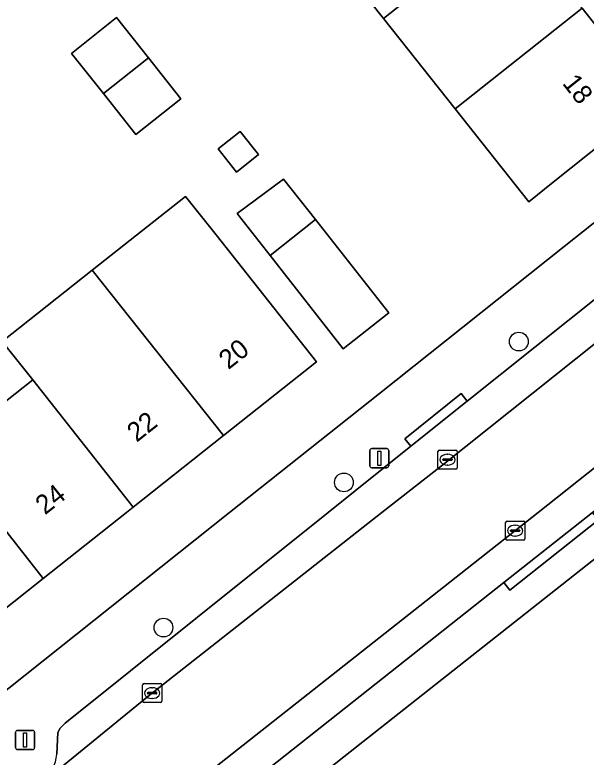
# Model space of a CAD drawing. Extents: x 157320 to 158835, y 386650 to 388491.
# Drawn here: x 157790.58 to 157820.38, y 387487.24 to 387525.96 of the extents above; entities that cross this region are included whole.
import ezdxf

# ---------------------------------------------------------------- set-up
doc = ezdxf.new("R2010")
doc.units = 0
for name, color, linetype in [('IMGEO_Boom', 7, 'Continuous'), ('IMGEO_Erf', 7, 'Continuous'), ('IMGEO_Kolk', 7, 'Continuous'), ('IMGEO_Lichtmast', 7, 'Continuous'), ('IMGEO_Muur', 7, 'Continuous'), ('IMGEO_Pand', 7, 'Continuous'), ('IMGEO_Pand_nummerreeks', 7, 'Continuous'), ('IMGEO_Parkeervlak_open', 7, 'Continuous'), ('IMGEO_Rijbaan_lokaal_open', 7, 'Continuous'), ('IMGEO_Voetpad_open', 7, 'Continuous')]:
    doc.layers.add(name, color=color, linetype=linetype)

msp = doc.modelspace()

# ---------------------------------------------------------------- linework, layer by layer
at = {"layer": 'IMGEO_Boom'}
for centre in [(157816.87, 387508.916), (157807.747, 387501.571), (157798.335, 387493.995)]:
    msp.add_circle(centre, 0.489, dxfattribs=at)
at = {"layer": 'IMGEO_Erf'}
for points in [[(157819.244, 387513.872), (157824.278, 387517.873), (157829.287, 387521.854), (157827.412, 387524.212), (157792.348, 387568.39), (157742.039, 387528.565), (157744.071, 387526.007), (157755.546, 387511.564), (157757.331, 387512.983), (157759.693, 387514.861), (157761.245, 387516.095), (157763.827, 387518.148), (157766.927, 387514.234), (157764.333, 387512.18), (157762.786, 387510.955), (157760.42, 387509.082), (157758.638, 387507.671), (157762.365, 387502.98), (157760.625, 387501.492), (157769.911, 387489.771), (157777.254, 387480.504), (157788.46, 387489.409), (157801.788, 387500), (157809.599, 387506.206)], [(157795.206, 387521.851), (157794.861, 387522.285), (157793.539, 387523.95), (157795.894, 387525.821), (157797.56, 387523.716), (157799.25, 387521.581), (157796.902, 387519.716)], [(157802.34, 387519.882), (157803.298, 387518.673), (157802.146, 387517.759), (157801.188, 387518.968)], [(157804.604, 387517.395), (157806.264, 387515.279), (157810.085, 387510.408), (157807.707, 387508.542), (157803.896, 387513.401), (157802.177, 387515.592)]]:
    msp.add_lwpolyline(points, close=True, dxfattribs=at)
for points in [[(157820.17, 387526.308), (157824.005, 387521.476), (157822.421, 387520.215), (157818.667, 387517.228), (157817.387, 387516.213), (157813.549, 387521.057), (157809.816, 387525.766), (157806.09, 387530.468)], [(157786.817, 387503.193), (157791.52, 387506.918), (157789.921, 387508.912), (157794.619, 387512.633), (157799.489, 387516.491), (157801.076, 387514.487), (157806.326, 387507.853), (157801.472, 387504.011), (157796.76, 387500.28), (157796.406, 387500), (157792.064, 387496.563), (157787.359, 387492.838)], [(157839.124, 387512.036), (157830.533, 387505.25), (157823.234, 387499.485), (157815.987, 387493.76), (157807.747, 387487.251), (157799.439, 387480.688)]]:
    msp.add_lwpolyline(points, dxfattribs=at)
at = {"layer": 'IMGEO_Kolk'}
for p, q in [((157812.726, 387503.256), (157813.578, 387503.256)), ((157812.651, 387502.33), (157812.651, 387503.182)), ((157813.139, 387503.036), (157813.164, 387503.036)), ((157813.652, 387503.182), (157813.652, 387502.33)), ((157812.91, 387502.75), (157812.91, 387502.762)), ((157813.348, 387502.713), (157812.95, 387502.713)), ((157812.953, 387502.799), (157813.351, 387502.799)), ((157813.162, 387502.476), (157813.137, 387502.476)), ((157813.394, 387502.762), (157813.394, 387502.75)), ((157813.578, 387502.256), (157812.726, 387502.256)), ((157816.18, 387498.627), (157816.18, 387499.479)), ((157816.255, 387499.553), (157817.107, 387499.553)), ((157817.181, 387499.479), (157817.181, 387498.627)), ((157816.439, 387499.047), (157816.439, 387499.059)), ((157816.877, 387499.01), (157816.479, 387499.01)), ((157816.482, 387499.096), (157816.88, 387499.096)), ((157816.668, 387499.333), (157816.693, 387499.333)), ((157816.923, 387499.059), (157816.923, 387499.047)), ((157816.691, 387498.773), (157816.666, 387498.773)), ((157817.107, 387498.553), (157816.255, 387498.553)), ((157797.246, 387490.156), (157797.246, 387491.008)), ((157797.321, 387491.082), (157798.173, 387491.082)), ((157797.734, 387490.862), (157797.759, 387490.862)), ((157798.247, 387491.008), (157798.247, 387490.156)), ((157797.505, 387490.576), (157797.505, 387490.588)), ((157797.943, 387490.539), (157797.545, 387490.539)), ((157797.548, 387490.625), (157797.946, 387490.625)), ((157797.989, 387490.588), (157797.989, 387490.576)), ((157798.173, 387490.082), (157797.321, 387490.082)), ((157797.757, 387490.302), (157797.732, 387490.302))]:
    msp.add_line(p, q, dxfattribs=at)
for points in [[(157812.726, 387503.256), (157813.578, 387503.256)], [(157812.651, 387502.33), (157812.651, 387503.182)], [(157813.652, 387503.182), (157813.652, 387502.33)], [(157813.578, 387502.256), (157812.726, 387502.256)], [(157816.18, 387498.627), (157816.18, 387499.479)], [(157816.255, 387499.553), (157817.107, 387499.553)], [(157817.181, 387499.479), (157817.181, 387498.627)], [(157817.107, 387498.553), (157816.255, 387498.553)], [(157797.246, 387490.156), (157797.246, 387491.008)], [(157797.321, 387491.082), (157798.173, 387491.082)], [(157798.247, 387491.008), (157798.247, 387490.156)], [(157798.173, 387490.082), (157797.321, 387490.082)]]:
    msp.add_lwpolyline(points, dxfattribs=at)
for centre, radius, start, end in [((157812.728, 387503.18), 0.0765, 91.552, 178.448), ((157812.728, 387503.18), 0.0765, 91.552, 178.448), ((157813.576, 387503.18), 0.0765, 1.552, 88.448), ((157813.576, 387503.18), 0.0765, 1.552, 88.448), ((157812.95, 387502.759), 0.0403, 85.8775, 175.7526), ((157812.947, 387502.749), 0.0366, 178.938, 274.7102), ((157813.351, 387502.756), 0.043, 264.8664, 352.4533), ((157813.355, 387502.761), 0.0386, 1.7309, 96.639), ((157812.728, 387502.332), 0.0765, 181.552, 268.448), ((157812.728, 387502.332), 0.0765, 181.552, 268.448), ((157813.576, 387502.332), 0.0765, 271.552, 358.448), ((157813.576, 387502.332), 0.0765, 271.552, 358.448), ((157816.257, 387499.477), 0.0765, 91.552, 178.448), ((157816.257, 387499.477), 0.0765, 91.552, 178.448), ((157817.105, 387499.477), 0.0765, 1.552, 88.448), ((157817.105, 387499.477), 0.0765, 1.552, 88.448), ((157816.479, 387499.056), 0.0403, 85.8775, 175.7526), ((157816.476, 387499.046), 0.0366, 178.938, 274.7102), ((157816.88, 387499.053), 0.043, 264.8664, 352.4533), ((157816.884, 387499.058), 0.0386, 1.7309, 96.639), ((157816.257, 387498.629), 0.0765, 181.552, 268.448), ((157816.257, 387498.629), 0.0765, 181.552, 268.448), ((157817.105, 387498.629), 0.0765, 271.552, 358.448), ((157817.105, 387498.629), 0.0765, 271.552, 358.448), ((157797.323, 387491.006), 0.0765, 91.552, 178.448), ((157797.323, 387491.006), 0.0765, 91.552, 178.448), ((157798.171, 387491.006), 0.0765, 1.552, 88.448), ((157798.171, 387491.006), 0.0765, 1.552, 88.448), ((157797.545, 387490.585), 0.0403, 85.8775, 175.7526), ((157797.542, 387490.575), 0.0366, 178.938, 274.7102), ((157797.946, 387490.582), 0.043, 264.8664, 352.4533), ((157797.95, 387490.587), 0.0386, 1.7309, 96.639), ((157797.323, 387490.158), 0.0765, 181.552, 268.448), ((157797.323, 387490.158), 0.0765, 181.552, 268.448), ((157798.171, 387490.158), 0.0765, 271.552, 358.448), ((157798.171, 387490.158), 0.0765, 271.552, 358.448)]:
    msp.add_arc(centre, radius, start, end, dxfattribs=at)
for centre, major_axis, ratio, start_param, end_param in [((157813.138, 387502.756), (-0.387, 0.002), 0.722429, 4.712389, 7.853982), ((157813.163, 387502.756), (-0.39, 0.002), 0.717154, 1.570796, 4.712389), ((157816.667, 387499.053), (-0.387, 0.002), 0.722429, 4.712389, 7.853982), ((157816.692, 387499.053), (-0.39, 0.002), 0.717154, 1.570796, 4.712389), ((157797.733, 387490.582), (-0.387, 0.002), 0.722429, 4.712389, 7.853982), ((157797.758, 387490.582), (-0.39, 0.002), 0.717154, 1.570796, 4.712389)]:
    msp.add_ellipse(centre, major_axis=major_axis, ratio=ratio, start_param=start_param, end_param=end_param, dxfattribs=at)
at = {"layer": 'IMGEO_Lichtmast'}
for p, q in [((157809.097, 387502.432), (157809.097, 387503.232)), ((157809.097, 387503.232), (157809.097, 387502.432)), ((157809.197, 387503.332), (157809.987, 387503.332)), ((157809.987, 387503.332), (157809.197, 387503.332)), ((157810.087, 387503.232), (157810.087, 387502.432)), ((157810.087, 387502.432), (157810.087, 387503.232)), ((157809.987, 387502.332), (157809.197, 387502.332)), ((157809.197, 387502.332), (157809.987, 387502.332)), ((157790.62, 387487.733), (157790.62, 387488.533)), ((157790.62, 387488.533), (157790.62, 387487.733)), ((157790.72, 387488.633), (157791.51, 387488.633)), ((157791.51, 387488.633), (157790.72, 387488.633)), ((157791.61, 387488.533), (157791.61, 387487.733)), ((157791.61, 387487.733), (157791.61, 387488.533)), ((157791.51, 387487.633), (157790.72, 387487.633)), ((157790.72, 387487.633), (157791.51, 387487.633))]:
    msp.add_line(p, q, dxfattribs=at)
for points in [[(157809.517, 387503.207), (157809.667, 387503.207), (157809.667, 387502.457), (157809.517, 387502.457), (157809.517, 387503.207)], [(157791.04, 387488.508), (157791.19, 387488.508), (157791.19, 387487.758), (157791.04, 387487.758), (157791.04, 387488.508)]]:
    msp.add_lwpolyline(points, dxfattribs=at)
for centre, start, end in [((157809.197, 387503.232), 90, 180), ((157809.197, 387503.232), 90, 180), ((157809.987, 387503.232), 0, 90), ((157809.987, 387503.232), 360, 90), ((157809.197, 387502.432), 180, 270), ((157809.197, 387502.432), 180, 270), ((157809.987, 387502.432), 270, 0), ((157809.987, 387502.432), 270, 0), ((157790.72, 387488.533), 90, 180), ((157790.72, 387488.533), 90, 180), ((157791.51, 387488.533), 0, 90), ((157791.51, 387488.533), 360, 90), ((157790.72, 387487.733), 180, 270), ((157790.72, 387487.733), 180, 270), ((157791.51, 387487.733), 270, 0), ((157791.51, 387487.733), 270, 0)]:
    msp.add_arc(centre, 0.1, start, end, dxfattribs=at)
at = {"layer": 'IMGEO_Muur'}
for points in [[(157809.599, 387506.206), (157819.244, 387513.872)], [(157815.987, 387493.76), (157807.747, 387487.251)]]:
    msp.add_lwpolyline(points, dxfattribs=at)
at = {"layer": 'IMGEO_Pand'}
for points in [[(157809.816, 387525.766), (157816.434, 387531.015), (157812.709, 387535.708), (157806.09, 387530.468)], [(157809.816, 387525.766), (157813.549, 387521.057), (157820.17, 387526.308), (157816.434, 387531.015)], [(157820.17, 387526.308), (157813.549, 387521.057), (157817.387, 387516.213), (157818.667, 387517.228), (157822.421, 387520.215), (157824.005, 387521.476)], [(157797.56, 387523.716), (157795.894, 387525.821), (157793.539, 387523.95), (157794.861, 387522.285), (157795.206, 387521.851)], [(157795.206, 387521.851), (157796.902, 387519.716), (157799.25, 387521.581), (157797.56, 387523.716)], [(157801.188, 387518.968), (157802.146, 387517.759), (157803.298, 387518.673), (157802.34, 387519.882)], [(157806.264, 387515.279), (157804.604, 387517.395), (157802.177, 387515.592), (157803.896, 387513.401)], [(157801.472, 387504.011), (157806.326, 387507.853), (157801.076, 387514.487), (157799.489, 387516.491), (157794.619, 387512.633)], [(157806.264, 387515.279), (157803.896, 387513.401), (157807.707, 387508.542), (157810.085, 387510.408)], [(157796.76, 387500.28), (157801.472, 387504.011), (157794.619, 387512.633), (157789.921, 387508.912), (157791.52, 387506.918)], [(157796.76, 387500.28), (157791.52, 387506.918), (157786.817, 387503.193), (157789.344, 387500), (157792.064, 387496.563), (157796.406, 387500)], [(157786.817, 387503.193), (157784.864, 387505.658), (157780.134, 387501.913), (157787.359, 387492.838), (157792.064, 387496.563), (157789.344, 387500)]]:
    msp.add_lwpolyline(points, close=True, dxfattribs=at)
at = {"layer": 'IMGEO_Parkeervlak_open'}
for points in [[(157834.45, 387513.15), (157817.884, 387500), (157797.32, 387483.775)], [(157792.118, 387485.993), (157797.613, 387490.476), (157809.73, 387500), (157812.992, 387502.564), (157824.461, 387511.695)], [(157821.228, 387511.435), (157814.172, 387505.812), (157811.243, 387503.454), (157806.928, 387500), (157793.202, 387489.013), (157792.943, 387488.745), (157792.83, 387488.527), (157792.777, 387487.386)], [(157798.55, 387483.955), (157799.605, 387483.712), (157799.929, 387483.776), (157800.357, 387483.896), (157816.093, 387496.341), (157820.714, 387500), (157833.408, 387510.077)]]:
    msp.add_lwpolyline(points, dxfattribs=at)
msp.add_arc((157790.268, 387487.721), 2.532, 316.9629, 352.4013, dxfattribs=at)
at = {"layer": 'IMGEO_Rijbaan_lokaal_open'}
for points in [[(157839.271, 387523.633), (157837.178, 387521.954), (157830.56, 387516.599), (157826.053, 387512.97), (157824.461, 387511.695), (157812.992, 387502.564), (157809.73, 387500), (157797.613, 387490.476), (157792.118, 387485.993), (157791.581, 387485.489), (157790.953, 387484.901)], [(157796.478, 387483.111), (157797.32, 387483.775), (157817.884, 387500), (157834.45, 387513.15)]]:
    msp.add_lwpolyline(points, dxfattribs=at)
at = {"layer": 'IMGEO_Voetpad_open'}
for points in [[(157826.053, 387512.97), (157830.56, 387516.599), (157829.906, 387517.407), (157836.524, 387522.762), (157835.189, 387524.078), (157830.517, 387520.307), (157829.287, 387521.854), (157824.278, 387517.873), (157819.244, 387513.872), (157809.599, 387506.206), (157801.788, 387500), (157788.46, 387489.409), (157777.254, 387480.504), (157775.948, 387479.466), (157780.901, 387473.236)], [(157799.439, 387480.688), (157807.747, 387487.251), (157815.987, 387493.76), (157823.234, 387499.485), (157830.533, 387505.25), (157839.124, 387512.036)], [(157792.777, 387487.386), (157792.83, 387488.527), (157792.943, 387488.745), (157793.202, 387489.013), (157806.928, 387500), (157811.243, 387503.454), (157810.93, 387503.843), (157813.859, 387506.201), (157814.172, 387505.812), (157821.228, 387511.435)], [(157833.408, 387510.077), (157820.714, 387500), (157821.024, 387499.609), (157816.403, 387495.95), (157816.093, 387496.341), (157800.357, 387483.896), (157799.929, 387483.776), (157799.605, 387483.712), (157798.55, 387483.955)]]:
    msp.add_lwpolyline(points, dxfattribs=at)
for points in [[(157811.243, 387503.454), (157814.172, 387505.812), (157813.859, 387506.201), (157810.93, 387503.843)], [(157820.714, 387500), (157816.093, 387496.341), (157816.403, 387495.95), (157821.024, 387499.609)]]:
    msp.add_lwpolyline(points, close=True, dxfattribs=at)
msp.add_arc((157790.268, 387487.721), 2.532, 316.9629, 352.4013, dxfattribs=at)

# ---------------------------------------------------------------- texts
at = {"layer": 'IMGEO_Pand_nummerreeks'}
for s, rotation, p in [('18', 308.438, (157819.102, 387522.378)), ('20', 38.3672, (157801.724, 387507.424)), ('22', 38.3672, (157796.937, 387503.634)), ('24', 38.4148, (157792.158, 387499.847))]:
    msp.add_text(s, height=1, rotation=rotation, dxfattribs=at).set_placement(p)

doc.saveas('drawing.dxf')
